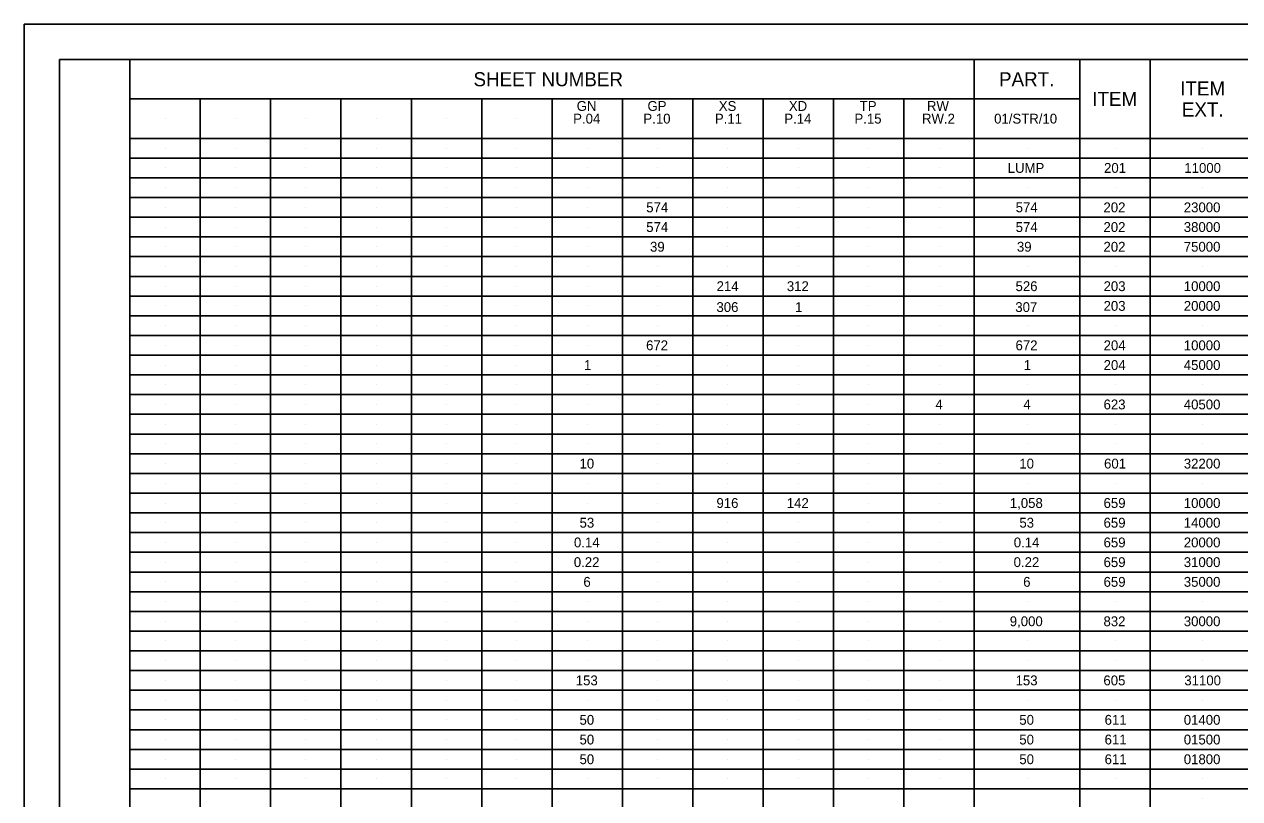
# Model space of a CAD drawing. Extents: x 0 to 34, y 0 to 22.
# Drawn here: x 0 to 17.27, y 11 to 22 of the extents above; entities that cross this region are included whole.
import ezdxf

# ---------------------------------------------------------------- set-up
doc = ezdxf.new("R2010")
doc.units = 0
for name, color, linetype in [('RD_P_Text', 7, 'Continuous'), ('SC_Scratch1', 7, 'Continuous'), ('SC_Scratch2', 7, 'Continuous'), ('SH_Border', 7, 'Continuous'), ('SH_Cut_Line', 7, 'Continuous'), ('SH_Data', 7, 'Continuous')]:
    doc.layers.add(name, color=color, linetype=linetype)

msp = doc.modelspace()

# ---------------------------------------------------------------- linework, layer by layer
at = {"layer": 'SC_Scratch1'}
for p, q in [((2, 20.66), (2, 20.66)), ((3, 20.66), (3, 20.66)), ((4, 20.66), (4, 20.66)), ((5, 20.66), (5, 20.66)), ((6, 20.66), (6, 20.66)), ((7, 20.66), (7, 20.66)), ((8, 20.66), (8, 20.66)), ((9, 20.66), (9, 20.66)), ((10, 20.66), (10, 20.66)), ((11, 20.66), (11, 20.66)), ((12, 20.66), (12, 20.66)), ((13, 20.66), (13, 20.66)), ((14.25, 20.66), (14.25, 20.66)), ((2, 20.24), (2, 20.24)), ((3, 20.24), (3, 20.24)), ((4, 20.24), (4, 20.24)), ((5, 20.24), (5, 20.24)), ((6, 20.24), (6, 20.24)), ((7, 20.24), (7, 20.24)), ((8, 20.24), (8, 20.24)), ((9, 20.24), (9, 20.24)), ((10, 20.24), (10, 20.24)), ((11, 20.24), (11, 20.24)), ((12, 20.24), (12, 20.24)), ((13, 20.24), (13, 20.24)), ((14.25, 20.24), (14.25, 20.24)), ((15.5, 20.24), (15.5, 20.24)), ((16.75, 20.24), (16.75, 20.24)), ((2, 19.96), (2, 19.96)), ((3, 19.96), (3, 19.96)), ((4, 19.96), (4, 19.96)), ((5, 19.96), (5, 19.96)), ((6, 19.96), (6, 19.96)), ((7, 19.96), (7, 19.96)), ((8, 19.96), (8, 19.96)), ((9, 19.96), (9, 19.96)), ((10, 19.96), (10, 19.96)), ((11, 19.96), (11, 19.96)), ((12, 19.96), (12, 19.96)), ((13, 19.96), (13, 19.96)), ((14.25, 19.96), (14.25, 19.96)), ((15.5, 19.96), (15.5, 19.96)), ((16.75, 19.96), (16.75, 19.96)), ((2, 19.68), (2, 19.68)), ((3, 19.68), (3, 19.68)), ((4, 19.68), (4, 19.68)), ((5, 19.68), (5, 19.68)), ((6, 19.68), (6, 19.68)), ((7, 19.68), (7, 19.68)), ((8, 19.68), (8, 19.68)), ((9, 19.68), (9, 19.68)), ((10, 19.68), (10, 19.68)), ((11, 19.68), (11, 19.68)), ((12, 19.68), (12, 19.68)), ((13, 19.68), (13, 19.68)), ((14.25, 19.68), (14.25, 19.68)), ((15.5, 19.68), (15.5, 19.68)), ((16.75, 19.68), (16.75, 19.68)), ((2, 19.4), (2, 19.4)), ((3, 19.4), (3, 19.4)), ((4, 19.4), (4, 19.4)), ((5, 19.4), (5, 19.4)), ((6, 19.4), (6, 19.4)), ((7, 19.4), (7, 19.4)), ((8, 19.4), (8, 19.4)), ((9, 19.4), (9, 19.4)), ((10, 19.4), (10, 19.4)), ((11, 19.4), (11, 19.4)), ((12, 19.4), (12, 19.4)), ((13, 19.4), (13, 19.4)), ((14.25, 19.4), (14.25, 19.4)), ((15.5, 19.4), (15.5, 19.4)), ((16.75, 19.4), (16.75, 19.4)), ((2, 19.12), (2, 19.12)), ((3, 19.12), (3, 19.12)), ((4, 19.12), (4, 19.12)), ((5, 19.12), (5, 19.12)), ((6, 19.12), (6, 19.12)), ((7, 19.12), (7, 19.12)), ((8, 19.12), (8, 19.12)), ((9, 19.12), (9, 19.12)), ((10, 19.12), (10, 19.12)), ((11, 19.12), (11, 19.12)), ((12, 19.12), (12, 19.12)), ((13, 19.12), (13, 19.12)), ((14.25, 19.12), (14.25, 19.12)), ((15.5, 19.12), (15.5, 19.12)), ((16.75, 19.12), (16.75, 19.12)), ((2, 18.84), (2, 18.84)), ((3, 18.84), (3, 18.84)), ((4, 18.84), (4, 18.84)), ((5, 18.84), (5, 18.84)), ((6, 18.84), (6, 18.84)), ((7, 18.84), (7, 18.84)), ((8, 18.84), (8, 18.84)), ((9, 18.84), (9, 18.84)), ((10, 18.84), (10, 18.84)), ((11, 18.84), (11, 18.84)), ((12, 18.84), (12, 18.84)), ((13, 18.84), (13, 18.84)), ((14.25, 18.84), (14.25, 18.84)), ((15.5, 18.84), (15.5, 18.84)), ((16.75, 18.84), (16.75, 18.84)), ((2, 18.56), (2, 18.56)), ((3, 18.56), (3, 18.56)), ((4, 18.56), (4, 18.56)), ((5, 18.56), (5, 18.56)), ((6, 18.56), (6, 18.56)), ((7, 18.56), (7, 18.56)), ((8, 18.56), (8, 18.56)), ((9, 18.56), (9, 18.56)), ((10, 18.56), (10, 18.56)), ((11, 18.56), (11, 18.56)), ((12, 18.56), (12, 18.56)), ((13, 18.56), (13, 18.56)), ((14.25, 18.56), (14.25, 18.56)), ((15.5, 18.56), (15.5, 18.56)), ((16.75, 18.56), (16.75, 18.56)), ((2, 18.28), (2, 18.28)), ((3, 18.28), (3, 18.28)), ((4, 18.28), (4, 18.28)), ((5, 18.28), (5, 18.28)), ((6, 18.28), (6, 18.28)), ((7, 18.28), (7, 18.28)), ((8, 18.28), (8, 18.28)), ((9, 18.28), (9, 18.28)), ((10, 18.28), (10, 18.28)), ((11, 18.28), (11, 18.28)), ((12, 18.28), (12, 18.28)), ((13, 18.28), (13, 18.28)), ((14.25, 18.28), (14.25, 18.28)), ((15.5, 18.28), (15.5, 18.28)), ((16.75, 18.28), (16.75, 18.28)), ((2, 18), (2, 18)), ((3, 18), (3, 18)), ((4, 18), (4, 18)), ((5, 18), (5, 18)), ((6, 18), (6, 18)), ((7, 18), (7, 18)), ((8, 18), (8, 18)), ((9, 18), (9, 18)), ((10, 18), (10, 18)), ((11, 18), (11, 18)), ((12, 18), (12, 18)), ((13, 18), (13, 18)), ((14.25, 18), (14.25, 18)), ((15.5, 18), (15.5, 18)), ((16.75, 18), (16.75, 18)), ((2, 17.72), (2, 17.72)), ((3, 17.72), (3, 17.72)), ((4, 17.72), (4, 17.72)), ((5, 17.72), (5, 17.72)), ((6, 17.72), (6, 17.72)), ((7, 17.72), (7, 17.72)), ((8, 17.72), (8, 17.72)), ((9, 17.72), (9, 17.72)), ((10, 17.72), (10, 17.72)), ((11, 17.72), (11, 17.72)), ((12, 17.72), (12, 17.72)), ((13, 17.72), (13, 17.72)), ((14.25, 17.72), (14.25, 17.72)), ((15.5, 17.72), (15.5, 17.72)), ((16.75, 17.72), (16.75, 17.72)), ((2, 17.44), (2, 17.44)), ((3, 17.44), (3, 17.44)), ((4, 17.44), (4, 17.44)), ((5, 17.44), (5, 17.44)), ((6, 17.44), (6, 17.44)), ((7, 17.44), (7, 17.44)), ((8, 17.44), (8, 17.44)), ((9, 17.44), (9, 17.44)), ((10, 17.44), (10, 17.44)), ((11, 17.44), (11, 17.44)), ((12, 17.44), (12, 17.44)), ((13, 17.44), (13, 17.44)), ((14.25, 17.44), (14.25, 17.44)), ((15.5, 17.44), (15.5, 17.44)), ((16.75, 17.44), (16.75, 17.44)), ((2, 17.16), (2, 17.16)), ((3, 17.16), (3, 17.16)), ((4, 17.16), (4, 17.16)), ((5, 17.16), (5, 17.16)), ((6, 17.16), (6, 17.16)), ((7, 17.16), (7, 17.16)), ((8, 17.16), (8, 17.16)), ((9, 17.16), (9, 17.16)), ((10, 17.16), (10, 17.16)), ((11, 17.16), (11, 17.16)), ((12, 17.16), (12, 17.16)), ((13, 17.16), (13, 17.16)), ((14.25, 17.16), (14.25, 17.16)), ((15.5, 17.16), (15.5, 17.16)), ((16.75, 17.16), (16.75, 17.16)), ((2, 16.88), (2, 16.88)), ((3, 16.88), (3, 16.88)), ((4, 16.88), (4, 16.88)), ((5, 16.88), (5, 16.88)), ((6, 16.88), (6, 16.88)), ((7, 16.88), (7, 16.88)), ((8, 16.88), (8, 16.88)), ((9, 16.88), (9, 16.88)), ((10, 16.88), (10, 16.88)), ((11, 16.88), (11, 16.88)), ((12, 16.88), (12, 16.88)), ((13, 16.88), (13, 16.88)), ((14.25, 16.88), (14.25, 16.88)), ((15.5, 16.88), (15.5, 16.88)), ((16.75, 16.88), (16.75, 16.88)), ((2, 16.6), (2, 16.6)), ((3, 16.6), (3, 16.6)), ((4, 16.6), (4, 16.6)), ((5, 16.6), (5, 16.6)), ((6, 16.6), (6, 16.6)), ((7, 16.6), (7, 16.6)), ((8, 16.6), (8, 16.6)), ((9, 16.6), (9, 16.6)), ((10, 16.6), (10, 16.6)), ((11, 16.6), (11, 16.6)), ((12, 16.6), (12, 16.6)), ((13, 16.6), (13, 16.6)), ((14.25, 16.6), (14.25, 16.6)), ((15.5, 16.6), (15.5, 16.6)), ((16.75, 16.6), (16.75, 16.6)), ((2, 16.32), (2, 16.32)), ((3, 16.32), (3, 16.32)), ((4, 16.32), (4, 16.32)), ((5, 16.32), (5, 16.32)), ((6, 16.32), (6, 16.32)), ((7, 16.32), (7, 16.32)), ((8, 16.32), (8, 16.32)), ((9, 16.32), (9, 16.32)), ((10, 16.32), (10, 16.32)), ((11, 16.32), (11, 16.32)), ((12, 16.32), (12, 16.32)), ((13, 16.32), (13, 16.32)), ((14.25, 16.32), (14.25, 16.32)), ((15.5, 16.32), (15.5, 16.32)), ((16.75, 16.32), (16.75, 16.32)), ((2, 16.04), (2, 16.04)), ((3, 16.04), (3, 16.04)), ((4, 16.04), (4, 16.04)), ((5, 16.04), (5, 16.04)), ((6, 16.04), (6, 16.04)), ((7, 16.04), (7, 16.04)), ((8, 16.04), (8, 16.04)), ((9, 16.04), (9, 16.04)), ((10, 16.04), (10, 16.04)), ((11, 16.04), (11, 16.04)), ((12, 16.04), (12, 16.04)), ((13, 16.04), (13, 16.04)), ((14.25, 16.04), (14.25, 16.04)), ((15.5, 16.04), (15.5, 16.04)), ((16.75, 16.04), (16.75, 16.04)), ((2, 15.76), (2, 15.76)), ((3, 15.76), (3, 15.76)), ((4, 15.76), (4, 15.76)), ((5, 15.76), (5, 15.76)), ((6, 15.76), (6, 15.76)), ((7, 15.76), (7, 15.76)), ((8, 15.76), (8, 15.76)), ((9, 15.76), (9, 15.76)), ((10, 15.76), (10, 15.76)), ((11, 15.76), (11, 15.76)), ((12, 15.76), (12, 15.76)), ((13, 15.76), (13, 15.76)), ((14.25, 15.76), (14.25, 15.76)), ((15.5, 15.76), (15.5, 15.76)), ((16.75, 15.76), (16.75, 15.76)), ((2, 15.48), (2, 15.48)), ((3, 15.48), (3, 15.48)), ((4, 15.48), (4, 15.48)), ((5, 15.48), (5, 15.48)), ((6, 15.48), (6, 15.48)), ((7, 15.48), (7, 15.48)), ((8, 15.48), (8, 15.48)), ((9, 15.48), (9, 15.48)), ((10, 15.48), (10, 15.48)), ((11, 15.48), (11, 15.48)), ((12, 15.48), (12, 15.48)), ((13, 15.48), (13, 15.48)), ((14.25, 15.48), (14.25, 15.48)), ((15.5, 15.48), (15.5, 15.48)), ((16.75, 15.48), (16.75, 15.48)), ((2, 15.2), (2, 15.2)), ((3, 15.2), (3, 15.2)), ((4, 15.2), (4, 15.2)), ((5, 15.2), (5, 15.2)), ((6, 15.2), (6, 15.2)), ((7, 15.2), (7, 15.2)), ((8, 15.2), (8, 15.2)), ((9, 15.2), (9, 15.2)), ((10, 15.2), (10, 15.2)), ((11, 15.2), (11, 15.2)), ((12, 15.2), (12, 15.2)), ((13, 15.2), (13, 15.2)), ((14.25, 15.2), (14.25, 15.2)), ((15.5, 15.2), (15.5, 15.2)), ((16.75, 15.2), (16.75, 15.2)), ((2, 14.92), (2, 14.92)), ((3, 14.92), (3, 14.92)), ((4, 14.92), (4, 14.92)), ((5, 14.92), (5, 14.92)), ((6, 14.92), (6, 14.92)), ((7, 14.92), (7, 14.92)), ((8, 14.92), (8, 14.92)), ((9, 14.92), (9, 14.92)), ((10, 14.92), (10, 14.92)), ((11, 14.92), (11, 14.92)), ((12, 14.92), (12, 14.92)), ((13, 14.92), (13, 14.92)), ((14.25, 14.92), (14.25, 14.92)), ((15.5, 14.92), (15.5, 14.92)), ((16.75, 14.92), (16.75, 14.92)), ((2, 14.64), (2, 14.64)), ((3, 14.64), (3, 14.64)), ((4, 14.64), (4, 14.64)), ((5, 14.64), (5, 14.64)), ((6, 14.64), (6, 14.64)), ((7, 14.64), (7, 14.64)), ((8, 14.64), (8, 14.64)), ((9, 14.64), (9, 14.64)), ((10, 14.64), (10, 14.64)), ((11, 14.64), (11, 14.64)), ((12, 14.64), (12, 14.64)), ((13, 14.64), (13, 14.64)), ((14.25, 14.64), (14.25, 14.64)), ((15.5, 14.64), (15.5, 14.64)), ((16.75, 14.64), (16.75, 14.64)), ((2, 14.36), (2, 14.36)), ((3, 14.36), (3, 14.36)), ((4, 14.36), (4, 14.36)), ((5, 14.36), (5, 14.36)), ((6, 14.36), (6, 14.36)), ((7, 14.36), (7, 14.36)), ((8, 14.36), (8, 14.36)), ((9, 14.36), (9, 14.36)), ((10, 14.36), (10, 14.36)), ((11, 14.36), (11, 14.36)), ((12, 14.36), (12, 14.36)), ((13, 14.36), (13, 14.36)), ((14.25, 14.36), (14.25, 14.36)), ((15.5, 14.36), (15.5, 14.36)), ((16.75, 14.36), (16.75, 14.36)), ((2, 14.08), (2, 14.08)), ((3, 14.08), (3, 14.08)), ((4, 14.08), (4, 14.08)), ((5, 14.08), (5, 14.08)), ((6, 14.08), (6, 14.08)), ((7, 14.08), (7, 14.08)), ((8, 14.08), (8, 14.08)), ((9, 14.08), (9, 14.08)), ((10, 14.08), (10, 14.08)), ((11, 14.08), (11, 14.08)), ((12, 14.08), (12, 14.08)), ((13, 14.08), (13, 14.08)), ((14.25, 14.08), (14.25, 14.08)), ((15.5, 14.08), (15.5, 14.08)), ((16.75, 14.08), (16.75, 14.08)), ((2, 13.8), (2, 13.8)), ((3, 13.8), (3, 13.8)), ((4, 13.8), (4, 13.8)), ((5, 13.8), (5, 13.8)), ((6, 13.8), (6, 13.8)), ((7, 13.8), (7, 13.8)), ((8, 13.8), (8, 13.8)), ((9, 13.8), (9, 13.8)), ((10, 13.8), (10, 13.8)), ((11, 13.8), (11, 13.8)), ((12, 13.8), (12, 13.8)), ((13, 13.8), (13, 13.8)), ((14.25, 13.8), (14.25, 13.8)), ((15.5, 13.8), (15.5, 13.8)), ((16.75, 13.8), (16.75, 13.8)), ((2, 13.52), (2, 13.52)), ((3, 13.52), (3, 13.52)), ((4, 13.52), (4, 13.52)), ((5, 13.52), (5, 13.52)), ((6, 13.52), (6, 13.52)), ((7, 13.52), (7, 13.52)), ((8, 13.52), (8, 13.52)), ((9, 13.52), (9, 13.52)), ((10, 13.52), (10, 13.52)), ((11, 13.52), (11, 13.52)), ((12, 13.52), (12, 13.52)), ((13, 13.52), (13, 13.52)), ((14.25, 13.52), (14.25, 13.52)), ((15.5, 13.52), (15.5, 13.52)), ((16.75, 13.52), (16.75, 13.52)), ((2, 13.24), (2, 13.24)), ((3, 13.24), (3, 13.24)), ((4, 13.24), (4, 13.24)), ((5, 13.24), (5, 13.24)), ((6, 13.24), (6, 13.24)), ((7, 13.24), (7, 13.24)), ((8, 13.24), (8, 13.24)), ((9, 13.24), (9, 13.24)), ((10, 13.24), (10, 13.24)), ((11, 13.24), (11, 13.24)), ((12, 13.24), (12, 13.24)), ((13, 13.24), (13, 13.24)), ((14.25, 13.24), (14.25, 13.24)), ((15.5, 13.24), (15.5, 13.24)), ((16.75, 13.24), (16.75, 13.24)), ((2, 12.96), (2, 12.96)), ((3, 12.96), (3, 12.96)), ((4, 12.96), (4, 12.96)), ((5, 12.96), (5, 12.96)), ((6, 12.96), (6, 12.96)), ((7, 12.96), (7, 12.96)), ((8, 12.96), (8, 12.96)), ((9, 12.96), (9, 12.96)), ((10, 12.96), (10, 12.96)), ((11, 12.96), (11, 12.96)), ((12, 12.96), (12, 12.96)), ((13, 12.96), (13, 12.96)), ((14.25, 12.96), (14.25, 12.96)), ((15.5, 12.96), (15.5, 12.96)), ((16.75, 12.96), (16.75, 12.96)), ((2, 12.68), (2, 12.68)), ((3, 12.68), (3, 12.68)), ((4, 12.68), (4, 12.68)), ((5, 12.68), (5, 12.68)), ((6, 12.68), (6, 12.68)), ((7, 12.68), (7, 12.68)), ((8, 12.68), (8, 12.68)), ((9, 12.68), (9, 12.68)), ((10, 12.68), (10, 12.68)), ((11, 12.68), (11, 12.68)), ((12, 12.68), (12, 12.68)), ((13, 12.68), (13, 12.68)), ((14.25, 12.68), (14.25, 12.68)), ((15.5, 12.68), (15.5, 12.68)), ((16.75, 12.68), (16.75, 12.68)), ((2, 12.4), (2, 12.4)), ((3, 12.4), (3, 12.4)), ((4, 12.4), (4, 12.4)), ((5, 12.4), (5, 12.4)), ((6, 12.4), (6, 12.4)), ((7, 12.4), (7, 12.4)), ((8, 12.4), (8, 12.4)), ((9, 12.4), (9, 12.4)), ((10, 12.4), (10, 12.4)), ((11, 12.4), (11, 12.4)), ((12, 12.4), (12, 12.4)), ((13, 12.4), (13, 12.4)), ((14.25, 12.4), (14.25, 12.4)), ((15.5, 12.4), (15.5, 12.4)), ((16.75, 12.4), (16.75, 12.4)), ((2, 12.12), (2, 12.12)), ((3, 12.12), (3, 12.12)), ((4, 12.12), (4, 12.12)), ((5, 12.12), (5, 12.12)), ((6, 12.12), (6, 12.12)), ((7, 12.12), (7, 12.12)), ((8, 12.12), (8, 12.12)), ((9, 12.12), (9, 12.12)), ((10, 12.12), (10, 12.12)), ((11, 12.12), (11, 12.12)), ((12, 12.12), (12, 12.12)), ((13, 12.12), (13, 12.12)), ((14.25, 12.12), (14.25, 12.12)), ((15.5, 12.12), (15.5, 12.12)), ((16.75, 12.12), (16.75, 12.12)), ((2, 11.84), (2, 11.84)), ((3, 11.84), (3, 11.84)), ((4, 11.84), (4, 11.84)), ((5, 11.84), (5, 11.84)), ((6, 11.84), (6, 11.84)), ((7, 11.84), (7, 11.84)), ((8, 11.84), (8, 11.84)), ((9, 11.84), (9, 11.84)), ((10, 11.84), (10, 11.84)), ((11, 11.84), (11, 11.84)), ((12, 11.84), (12, 11.84)), ((13, 11.84), (13, 11.84)), ((14.25, 11.84), (14.25, 11.84)), ((15.5, 11.84), (15.5, 11.84)), ((16.75, 11.84), (16.75, 11.84)), ((2, 11.56), (2, 11.56)), ((3, 11.56), (3, 11.56)), ((4, 11.56), (4, 11.56)), ((5, 11.56), (5, 11.56)), ((6, 11.56), (6, 11.56)), ((7, 11.56), (7, 11.56)), ((8, 11.56), (8, 11.56)), ((9, 11.56), (9, 11.56)), ((10, 11.56), (10, 11.56)), ((11, 11.56), (11, 11.56)), ((12, 11.56), (12, 11.56)), ((13, 11.56), (13, 11.56)), ((14.25, 11.56), (14.25, 11.56)), ((15.5, 11.56), (15.5, 11.56)), ((16.75, 11.56), (16.75, 11.56)), ((2, 11.28), (2, 11.28)), ((3, 11.28), (3, 11.28)), ((4, 11.28), (4, 11.28)), ((5, 11.28), (5, 11.28)), ((6, 11.28), (6, 11.28)), ((7, 11.28), (7, 11.28)), ((8, 11.28), (8, 11.28)), ((9, 11.28), (9, 11.28)), ((10, 11.28), (10, 11.28)), ((11, 11.28), (11, 11.28)), ((12, 11.28), (12, 11.28)), ((13, 11.28), (13, 11.28)), ((14.25, 11.28), (14.25, 11.28)), ((15.5, 11.28), (15.5, 11.28)), ((16.75, 11.28), (16.75, 11.28)), ((16.75, 11), (16.75, 11))]:
    msp.add_line(p, q, dxfattribs=at)
at = {"layer": 'SH_Border'}
for points in [[(0.5, 21.5), (1.5, 21.5), (1.5, 0.5), (0.5, 0.5)], [(1.5, 21.5), (33.5, 21.5), (33.5, 0.5), (1.5, 0.5)]]:
    msp.add_lwpolyline(points, close=True, dxfattribs=at)
at = {"layer": 'SH_Cut_Line'}
msp.add_lwpolyline([(0, 0), (34, 0), (34, 22), (0, 22)], close=True, dxfattribs=at)
at = {"layer": 'SH_Data'}
for p, q in [((13.5, 21.5), (13.5, 0.5)), ((15, 21.5), (15, 0.5)), ((16, 21.5), (16, 0.5)), ((15, 20.94), (1.5, 20.94)), ((2.5, 20.94), (2.5, 0.5)), ((3.5, 20.94), (3.5, 0.5)), ((4.5, 20.94), (4.5, 0.5)), ((5.5, 20.94), (5.5, 0.5)), ((6.5, 20.94), (6.5, 0.5)), ((7.5, 20.94), (7.5, 0.5)), ((8.5, 20.94), (8.5, 0.5)), ((9.5, 20.94), (9.5, 0.5)), ((10.5, 20.94), (10.5, 0.5)), ((11.5, 20.94), (11.5, 0.5)), ((12.5, 20.94), (12.5, 0.5)), ((32, 20.38), (1.5, 20.38)), ((32, 20.1), (1.5, 20.1)), ((32, 19.82), (1.5, 19.82)), ((32, 19.54), (1.5, 19.54)), ((32, 19.26), (1.5, 19.26)), ((32, 18.98), (1.5, 18.98)), ((32, 18.7), (1.5, 18.7)), ((32, 18.42), (1.5, 18.42)), ((32, 18.14), (1.5, 18.14)), ((32, 17.86), (1.5, 17.86)), ((32, 17.58), (1.5, 17.58)), ((32, 17.3), (1.5, 17.3)), ((32, 17.02), (1.5, 17.02)), ((32, 16.74), (1.5, 16.74)), ((32, 16.46), (1.5, 16.46)), ((32, 16.18), (1.5, 16.18)), ((32, 15.9), (1.5, 15.9)), ((32, 15.62), (1.5, 15.62)), ((32, 15.34), (1.5, 15.34)), ((32, 15.06), (1.5, 15.06)), ((32, 14.78), (1.5, 14.78)), ((32, 14.5), (1.5, 14.5)), ((32, 14.22), (1.5, 14.22)), ((32, 13.94), (1.5, 13.94)), ((32, 13.66), (1.5, 13.66)), ((32, 13.38), (1.5, 13.38)), ((32, 13.1), (1.5, 13.1)), ((32, 12.82), (1.5, 12.82)), ((32, 12.54), (1.5, 12.54)), ((32, 12.26), (1.5, 12.26)), ((32, 11.98), (1.5, 11.98)), ((32, 11.7), (1.5, 11.7)), ((32, 11.42), (1.5, 11.42)), ((32, 11.14), (1.5, 11.14))]:
    msp.add_line(p, q, dxfattribs=at)

# ---------------------------------------------------------------- texts
at = {"layer": 'RD_P_Text'}
for s, p in [('P.04', (7.8, 20.59)), ('P.10', (8.798, 20.59)), ('P.11', (9.814, 20.59)), ('P.14', (10.8, 20.59)), ('P.15', (11.797, 20.59)), ('RW.2', (12.757, 20.59)), ('01/STR/10', (13.782, 20.59)), ('LUMP', (13.975, 19.89)), ('201', (15.344, 19.89)), ('11000', (16.485, 19.89)), ('574', (8.838, 19.33)), ('574', (14.088, 19.33)), ('202', (15.336, 19.33)), ('23000', (16.477, 19.33)), ('574', (8.838, 19.05)), ('574', (14.088, 19.05)), ('202', (15.336, 19.05)), ('38000', (16.477, 19.05)), ('39', (8.892, 18.77)), ('39', (14.106, 18.77)), ('202', (15.336, 18.77)), ('75000', (16.477, 18.77)), ('214', (9.838, 18.21)), ('312', (10.836, 18.21)), ('526', (14.086, 18.21)), ('203', (15.337, 18.21)), ('10000', (16.477, 18.21)), ('306', (9.836, 17.913)), ('1', (10.953, 17.913)), ('307', (14.083, 17.913)), ('203', (15.337, 17.93)), ('20000', (16.477, 17.93)), ('672', (8.836, 17.37)), ('672', (14.086, 17.37)), ('204', (15.338, 17.37)), ('10000', (16.477, 17.37)), ('1', (7.953, 17.09)), ('1', (14.203, 17.09)), ('204', (15.338, 17.09)), ('45000', (16.477, 17.09)), ('4', (12.947, 16.53)), ('4', (14.197, 16.53)), ('623', (15.337, 16.53)), ('40500', (16.477, 16.53)), ('10', (7.89, 15.69)), ('10', (14.14, 15.69)), ('601', (15.344, 15.69)), ('32200', (16.477, 15.69)), ('916', (9.836, 15.13)), ('142', (10.836, 15.13)), ('1,058', (14.005, 15.13)), ('659', (15.337, 15.13)), ('10000', (16.477, 15.13)), ('53', (7.891, 14.85)), ('53', (14.141, 14.85)), ('659', (15.337, 14.85)), ('14000', (16.477, 14.85)), ('0.14', (7.811, 14.57)), ('0.14', (14.061, 14.57)), ('659', (15.337, 14.57)), ('20000', (16.477, 14.57)), ('0.22', (7.809, 14.29)), ('0.22', (14.059, 14.29)), ('659', (15.337, 14.29)), ('31000', (16.477, 14.29)), ('6', (7.945, 14.01)), ('6', (14.195, 14.01)), ('659', (15.337, 14.01)), ('35000', (16.477, 14.01)), ('9,000', (14.004, 13.45)), ('832', (15.336, 13.45)), ('30000', (16.477, 13.45)), ('153', (7.837, 12.61)), ('153', (14.087, 12.61)), ('605', (15.335, 12.61)), ('31100', (16.485, 12.61)), ('50', (7.89, 12.05)), ('50', (14.14, 12.05)), ('611', (15.352, 12.05)), ('01400', (16.477, 12.05)), ('50', (7.89, 11.77)), ('50', (14.14, 11.77)), ('611', (15.352, 11.77)), ('01500', (16.477, 11.77)), ('50', (7.89, 11.49)), ('50', (14.14, 11.49)), ('611', (15.352, 11.49)), ('01800', (16.477, 11.49))]:
    msp.add_text(s, height=0.14, dxfattribs=at).set_placement(p)
at = {"layer": 'SC_Scratch2'}
for s, p in [('GN', (7.85, 20.77)), ('GP', (8.856, 20.77)), ('XS', (9.869, 20.77)), ('XD', (10.865, 20.77)), ('TP', (11.872, 20.77)), ('RW', (12.827, 20.77))]:
    msp.add_text(s, height=0.14, dxfattribs=at).set_placement(p)
at = {"layer": 'SH_Data'}
for s, p in [('SHEET NUMBER', (6.383, 21.12)), ('PART.', (13.851, 21.12)), ('ITEM', (16.426, 20.99)), ('ITEM', (15.176, 20.84)), ('EXT.', (16.449, 20.69))]:
    msp.add_text(s, height=0.2, dxfattribs=at).set_placement(p)

doc.saveas('drawing.dxf')
